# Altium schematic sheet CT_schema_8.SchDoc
size 254 x 194 mm
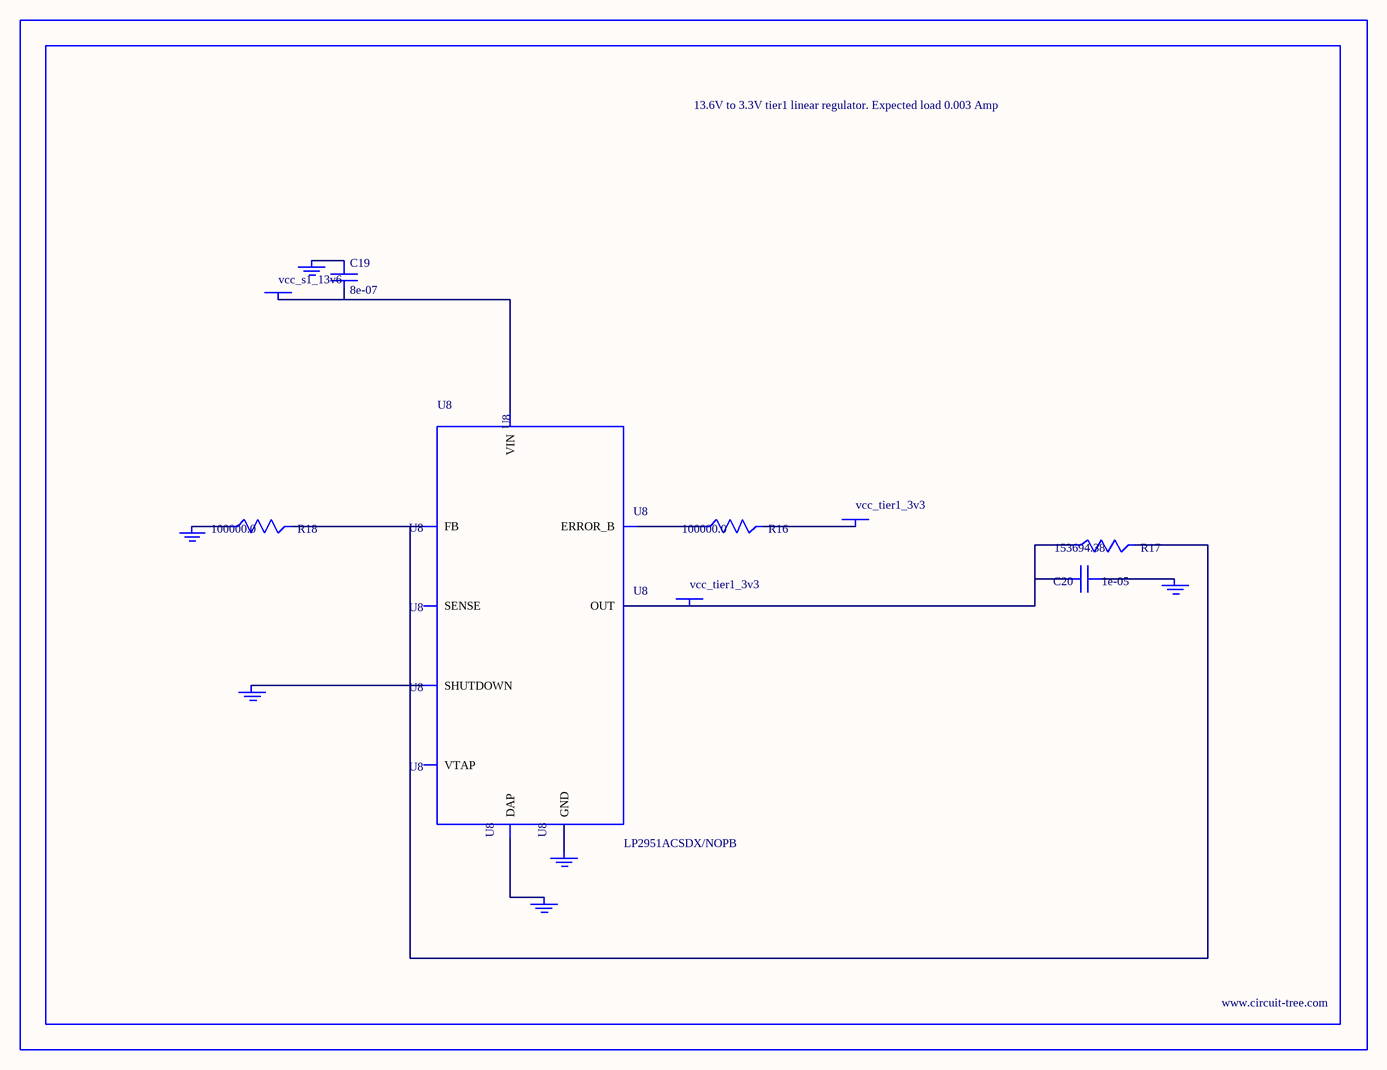
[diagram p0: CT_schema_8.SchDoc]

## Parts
BORDER7  (no value)
C19  8e-07  [R0603]
C20  1e-05  [C1210]
GND_INSTANCE_7_0  (no value)
GND_INSTANCE_7_1  (no value)
GND_INSTANCE_7_2  (no value)
GND_INSTANCE_7_3  (no value)
GND_INSTANCE_7_4  (no value)
GND_INSTANCE_7_5  (no value)
POWER_INSTANCE_7_0  vcc_tier1_3v3
POWER_INSTANCE_7_1  vcc_s1_13v6
POWER_INSTANCE_7_2  vcc_tier1_3v3
R16  100000.0  [R0603]
R17  153694.38  [R0603]
R18  100000.0  [R0603]
U8  LP2951ACSDX/NOPB  [WSON-8]

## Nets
NetC19_1: C19.1 GND_INSTANCE_7_3.0(GND)
NetC19_2: C19.2 POWER_INSTANCE_7_1.0(PWR) U8.8(VIN)
NetC20_1: C20.1 GND_INSTANCE_7_0.0(GND)
NetC20_2: C20.2 POWER_INSTANCE_7_2.0(PWR) R17.1 U8.1(OUT)
NetGND_INSTANCE_7_1_0: GND_INSTANCE_7_1.0(GND) U8.3(SHUTDOWN)
NetGND_INSTANCE_7_2_0: GND_INSTANCE_7_2.0(GND) R18.1
NetGND_INSTANCE_7_4_0: GND_INSTANCE_7_4.0(GND) U8.PAD(DAP)
NetGND_INSTANCE_7_5_0: GND_INSTANCE_7_5.0(GND) U8.4(GND)
NetPOWER_INSTANCE_7_0_0: POWER_INSTANCE_7_0.0(PWR) R16.2
NetR16_1: R16.1 U8.5(ERROR_B)
NetR17_2: R17.2 R18.2 U8.7(FB)

Not connected (* = marked no-connect by the designer): U8 2(SENSE) 6(VTAP)

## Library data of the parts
BORDER7 = BORDER_PAGE7
C19 = C19
C20 = GRM32DR61E106MA12L
GND_INSTANCE_7_0-GND_INSTANCE_7_5 = GND
POWER_INSTANCE_7_0-POWER_INSTANCE_7_2 = PWR
R16 R18 = RC0603JR-07100KL
R17 = R17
